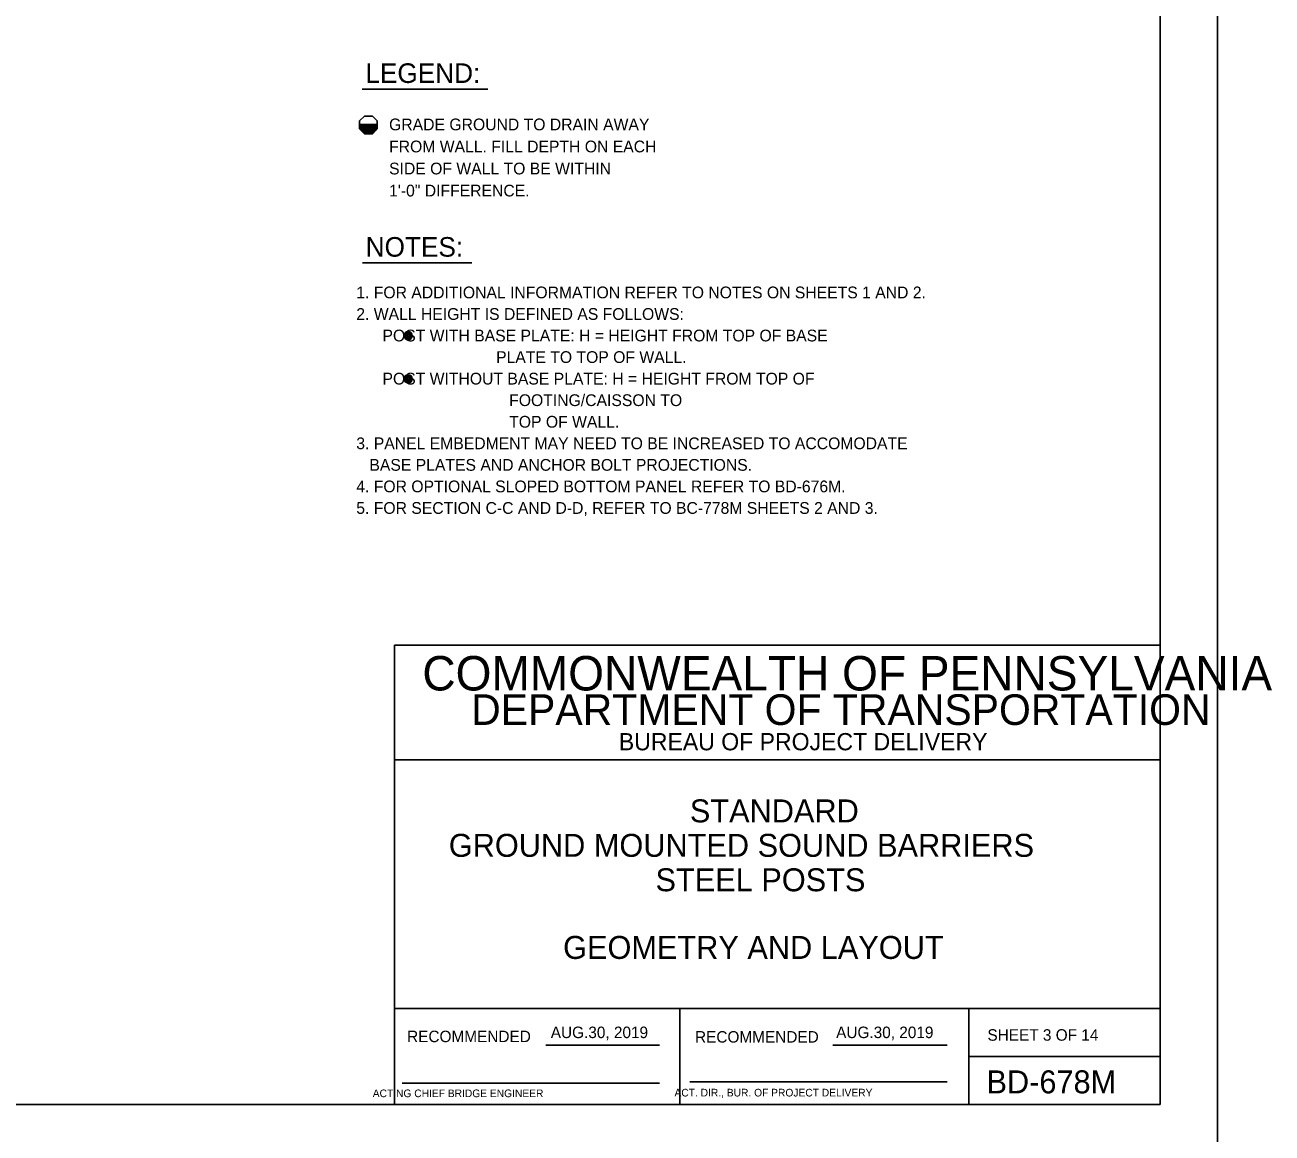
# Model space of a CAD drawing. Extents: x 3475 to 6558, y -3780 to 1166.
# Drawn here: x 4290.8 to 4616.6, y -14.8 to 274.7 of the extents above; entities that cross this region are included whole.
import ezdxf

# ---------------------------------------------------------------- set-up
doc = ezdxf.new("R2010")
doc.units = 0
for name, color, linetype in [('1', 7, 'Continuous'), ('2', 7, 'Continuous'), ('PLT-BNDY', 7, 'Continuous')]:
    doc.layers.add(name, color=color, linetype=linetype)

msp = doc.modelspace()

# ---------------------------------------------------------------- linework, layer by layer
at = {"layer": '1'}
for p, q in [((4378.9, 257.91), (4411.7, 257.91)), ((4379.45, 250.9), (4378.2, 249.65)), ((4379.45, 250.9), (4381.57, 250.9)), ((4381.57, 250.9), (4382.82, 249.65)), ((4378.19, 248.71), (4382.81, 248.71)), ((4378.19, 247.81), (4382.81, 247.81)), ((4378.19, 247.71), (4382.81, 247.71)), ((4378.2, 249.65), (4378.2, 247.53)), ((4378.2, 248.31), (4382.81, 248.31)), ((4378.2, 248.21), (4382.81, 248.21)), ((4378.2, 248.11), (4382.81, 248.11)), ((4378.2, 248.01), (4382.81, 248.01)), ((4378.2, 247.91), (4382.81, 247.91)), ((4378.21, 248.61), (4382.81, 248.61)), ((4378.21, 248.51), (4382.81, 248.51)), ((4378.21, 248.41), (4382.81, 248.41)), ((4381.29, 248.71), (4382.81, 248.71)), ((4382.82, 249.65), (4382.82, 247.53)), ((4378.19, 247.61), (4382.81, 247.61)), ((4379.45, 246.28), (4378.2, 247.53)), ((4378.21, 247.51), (4382.76, 247.51)), ((4378.31, 247.41), (4382.67, 247.41)), ((4378.41, 247.31), (4382.57, 247.31)), ((4378.51, 247.21), (4382.48, 247.21)), ((4378.62, 247.11), (4382.38, 247.11)), ((4378.72, 247.01), (4382.28, 247.01)), ((4378.82, 246.91), (4382.19, 246.91)), ((4378.92, 246.81), (4382.09, 246.81)), ((4379.02, 246.71), (4381.99, 246.71)), ((4379.13, 246.61), (4381.9, 246.61)), ((4379.23, 246.51), (4381.8, 246.51)), ((4379.33, 246.41), (4381.71, 246.41)), ((4379.43, 246.31), (4381.61, 246.31)), ((4379.45, 246.28), (4381.57, 246.28)), ((4381.57, 246.28), (4382.82, 247.53)), ((4378.94, 212.53), (4407.51, 212.53))]:
    msp.add_line(p, q, dxfattribs=at)
for centre, radius in [((4390.89, 193.5), 1.07), ((4390.89, 193.5), 0.8), ((4390.89, 193.5), 0.533), ((4390.89, 193.5), 0.267), ((4390.89, 182.24), 1.07), ((4390.89, 182.24), 0.8), ((4390.89, 182.24), 0.533), ((4390.89, 182.24), 0.267)]:
    msp.add_circle(centre, radius, dxfattribs=at)
at = {"layer": '2'}
for p, q in [((4587.34, 556.69), (4587.34, -7.31)), ((4587.34, 112.69), (4387.34, 112.69)), ((4387.34, 112.69), (4387.34, -7.31)), ((4587.34, -7.31), (4587.34, 112.69)), ((4587.34, 82.69), (4387.34, 82.69)), ((4587.34, 17.69), (4387.34, 17.69)), ((4461.84, -7.31), (4461.84, 17.69)), ((4537.34, 17.69), (4537.34, -7.31)), ((4426.81, 8.19), (4456.57, 8.19)), ((4501.81, 8.19), (4531.71, 8.19)), ((4537.34, 5.19), (4587.34, 5.19)), ((4389.34, -1.81), (4456.57, -1.81)), ((4464.47, -1.43), (4531.71, -1.43)), ((4587.34, -7.31), (3801.34, -7.31)), ((4387.34, -7.31), (4587.34, -7.31))]:
    msp.add_line(p, q, dxfattribs=at)
at = {"layer": 'PLT-BNDY'}
msp.add_lwpolyline([(3761.34, 571.69), (4602.34, 571.69), (4602.34, -22.31), (3761.34, -22.31)], close=True, dxfattribs=at)

# ---------------------------------------------------------------- texts
at = {"layer": '1'}
for s, height, p in [('LEGEND:', 5.117, (4379.7, 259.54)), ('GRADE GROUND TO DRAIN AWAY', 3.072, (4385.9, 247.16)), ('FROM WALL. FILL DEPTH ON EACH', 3.072, (4385.9, 241.4)), ('SIDE OF WALL TO BE WITHIN', 3.072, (4385.9, 235.64)), ('1\'-0" DIFFERENCE.', 3.072, (4385.9, 229.88)), ('NOTES:', 5.117, (4379.78, 214.15)), ('1. FOR ADDITIONAL INFORMATION REFER TO NOTES ON SHEETS 1 AND 2.', 3.072, (4377.33, 203.27)), ('2. WALL HEIGHT IS DEFINED AS FOLLOWS:', 3.072, (4377.33, 197.64)), ('      POST WITH BASE PLATE: H = HEIGHT FROM TOP OF BASE', 3.072, (4377.33, 192.01)), ('                                PLATE TO TOP OF WALL.', 3.072, (4377.33, 186.38)), ('      POST WITHOUT BASE PLATE: H = HEIGHT FROM TOP OF ', 3.072, (4377.33, 180.75)), ('                                   FOOTING/CAISSON TO', 3.072, (4377.33, 175.12)), ('                                   TOP OF WALL.', 3.072, (4377.33, 169.48)), ('3. PANEL EMBEDMENT MAY NEED TO BE INCREASED TO ACCOMODATE', 3.072, (4377.33, 163.85)), ('   BASE PLATES AND ANCHOR BOLT PROJECTIONS.', 3.072, (4377.33, 158.22)), ('4. FOR OPTIONAL SLOPED BOTTOM PANEL REFER TO BD-676M. ', 3.072, (4377.33, 152.59)), ('5. FOR SECTION C-C AND D-D, REFER TO BC-778M SHEETS 2 AND 3.', 3.072, (4377.33, 146.96)), ('STANDARD', 6, (4464.48, 66.36)), ('GROUND MOUNTED SOUND BARRIERS', 6.0001, (4401.5, 57.36)), ('STEEL POSTS', 6.0001, (4455.5, 48.36)), ('GEOMETRY AND LAYOUT', 6.0001, (4431.36, 30.69)), ('SHEET 3 OF 14', 3, (4542.22, 9.32)), ('BD-678M', 6, (4541.97, -4.43))]:
    msp.add_text(s, height=height, dxfattribs=at).set_placement(p)
at = {"layer": '2'}
for s, height, p in [('COMMONWEALTH OF PENNSYLVANIA', 9, (4394.59, 100.82)), ('DEPARTMENT OF TRANSPORTATION', 8.0002, (4407.34, 91.82)), ('BUREAU OF PROJECT DELIVERY', 4.5, (4445.93, 85.19)), ('AUG.30, 2019', 3, (4428.14, 10)), ('AUG.30, 2019', 3, (4502.69, 10)), ('   ACT. DIR., BUR. OF PROJECT DELIVERY', 2.0002, (4458.23, -5.25)), ('       ACTING CHIEF BRIDGE ENGINEER', 2.0002, (4376.43, -5.43))]:
    msp.add_text(s, height=height, dxfattribs=at).set_placement(p)
for p in [(4390.61, 8.94), (4465.83, 8.82)]:
    msp.add_text('RECOMMENDED', height=3, rotation=360, dxfattribs=at).set_placement(p)

doc.saveas('drawing.dxf')
